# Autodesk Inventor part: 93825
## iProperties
Author: Administrator
Shininess: 64.0
Angle Display Precision: 2
Document Length Units: 11272
Document Angle Units: 11286
Document Time Units: 11279
Document Mass Units: 11290
Document Length Units Precision: 3
Document Angle Units Precision: 2
Compacted: True
PropertySet Name: _Private Model Information
Created: 2002-03
Part Number: 93825
Material: Stainless Steel, 440C
Document SubType Name: Modeling
Designer: Administrator
Control State: 0
Master: False
Checked Out: False
PropertySet Name: Design Tracking Control
Density: 0.0
Volumn: 0.0
Area: 0.0
PropertySet Name: Model Information
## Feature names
1. Revolution1
